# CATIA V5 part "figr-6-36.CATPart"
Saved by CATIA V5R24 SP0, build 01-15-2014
Part number: Part1
Bounding box of the stored display mesh (mm): x -40.3 to 40.3, y -45.975 to 45.975, z 0 to 40
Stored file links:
  D:\KAVITA\CATIA V5-6R2014 Project_ Kavita\CATIA V5-6R2014_partfiles\Partfiles\c06_catia_v5-6r2014_prt\figr-6-36.CATPart
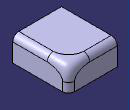
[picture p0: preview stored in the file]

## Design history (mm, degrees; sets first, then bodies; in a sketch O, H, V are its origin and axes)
Body1 (main body)
  Sketch1 on xy-plane, origin (0, 0, 0), H (1, 0, 0), V (0, 1, 0)
    line L1 (-40.2998, 45.9753) -> (40.2998, 45.9753)
    line L2 (40.2998, 45.9753) -> (40.2998, -45.9753)
    line L3 (40.2998, -45.9753) -> (-40.2998, -45.9753)
    line L4 (-40.2998, -45.9753) -> (-40.2998, 45.9753)
    axis line L5 (40.2998, -45.9753) -> (-40.2998, 45.9753)
    horizontal: L1 H, L3 H
    vertical: L2 V, L4 V
    midpoint: O L5
  Pad1: profile Sketch1, direction (0, 0, 1), length 40
  Fillet1: radius 10, on edge [face of Pad1 | face of Pad1] (x3)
